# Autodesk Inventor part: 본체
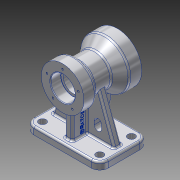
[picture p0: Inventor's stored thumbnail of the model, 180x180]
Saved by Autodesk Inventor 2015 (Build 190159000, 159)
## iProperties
Created: 2015-08
Part Number: 본체
Material: Aluminum 6061
Document SubType Name: Modeling
Designer: 601
Density: 2.7 g/cm^3
Appearance: Aluminum - Flat
Mass: 1058.96 g
Surface Area: 767.525 cm^2
Volume: 392.208 cm^3
Author: 601
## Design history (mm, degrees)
sketch "Sketch3"
  geometry: L1 (20, -5.906)-(20, -22.906); L2 (20, -22.906)-(16, -22.906); L3 (16, -22.906)-(16, -72.906); L4 (0, 0)-(0, -90); L5 (26, -95.906)-(26, -75.906); L6 (35, -5.906)-(35, -25.906); L7 (26, -95.906)-(40, -95.906); L8 (40, -95.906)-(40, -75.906); L9 (26.173, -31.002)-(35, -25.906); L10 (26.173, -59.428)-(40, -75.906); L11 (20, -17.072)-(20, -22.906); L12 (26.173, -31.002)-(26.173, -59.428); L13 (35, -5.906)-(20, -5.906); L14 (26, -75.906)-(19, -75.906); L15 (19, -75.906)-(19, -72.906); L16 (19, -72.906)-(16, -72.906)
  constraints: 32 end point, 7 vertical, 4 horizontal, 3 perpendicular
  dimensions: "d31" = 17 distance of L1.start L1.end; "d32" = 20 distance from line of L4.start L1; "d36" = 90 distance of L4.start L4.end; "d38" = 26 distance between parallel lines of L4 L5; "d39" = 20 distance of L6.start L6.end; "d40" = 35 distance between parallel lines of L4 L6; "d45" = 20 distance of L7.end L8.end; "d46" = 40 distance from line of L4 L7.end; "d132" = 90 distance between parallel lines of L7 L13; "d133" = 60 deg angle of L12 L9; "d134" = 40 deg angle of L12 L10; "d135" = 7 distance of L5.end L14.end; "d138" = 16 distance between parallel lines of L4 L3; "d139" = 50 distance between parallel lines of L2 L16; "d140" = 26.17342 distance between parallel lines of L4 L12
revolve "Revolution2" sketch "Sketch3" stored, may be unused: angle "d50" = 90 deg
workplane "Work Plane2"
sketch "Sketch7"
  geometry: L1 (-47, -85.906)-(47, -85.906); L2 (61, -71.906)-(61, -19.906); L3 (47, -5.906)-(-47, -5.906); L4 (-61, -19.906)-(-61, -71.906); C1 r 6 at (47, -71.906); C2 r 6 at (47, -19.906); C3 r 6 at (-47, -71.906); C4 r 6 at (-47, -19.906); A1 r 14 centre (-47, -19.906) between (-47, -5.906) and (-61, -19.906); A2 r 14 centre (47, -19.906) between (61, -19.906) and (47, -5.906); A3 r 14 centre (47, -71.906) between (47, -85.906) and (61, -71.906); A4 r 14 centre (-47, -71.906) between (-61, -71.906) and (-47, -85.906); 6 further points; 1 other entity
  constraints: 8 centre point, 8 end point, 8 point on circle, 8 tangent, 6 point on line, 5 equal radius, 2 horizontal alignment, 2 parallel, 1 coincident, 1 horizontal, 1 perpendicular, 1 vertical, 3 other
  dimensions: "d76" = 122 distance of point (-61, -5.906) point (61, -5.906); "d77" = 80 distance of point (61, -5.906) point (61, -85.906); "d78" = 80 dimension on L1; "d79" = 61 distance from line of point (0, 0) L4; "d80" = 14 radius of A1; "d81" = 12 diameter of C1; "d84" = 52 distance of C1.centre C2.centre; "d87" = 94 distance of C1.centre C3.centre
extrude "Extrusion2" join sketch "Sketch7" distance "d90" = 12; taper "d91" = 0 deg
workplane "Work Plane4"
sketch "Sketch8"
  geometry: L1 (108, 0)-(108, 12) reference; L2 (-14, 0)-(-14, 12) reference; L3 (0, 12)-(94, 12) reference; L4 (72.193, 82.904)-(98, 12); L5 (21.807, 82.904)-(-4, 12); L6 (-4, 12)-(98, 12); L7 (65, 30)-(65, 36); L8 (77, 30)-(77, 36); L9 (47, 90)-(47, 12); L10 (17.016, 36.433)-(17.016, 30.433); L11 (28.984, 36.433)-(28.984, 29.567); A1 r 26.173 centre (47, 90) between (72.193, 82.904) and (21.807, 82.904) reference; A2 r 26.173 centre (47, 90) between (21.807, 82.904) and (72.193, 82.904); A3 r 6 centre (71, 36) between (77, 36) and (65, 36); A4 r 6 centre (71, 30) between (65, 30) and (77, 30); A5 r 6 centre (23, 36) between (28.984, 35.567) and (17.016, 35.567); A6 r 6 centre (23, 30) between (17.016, 30.433) and (28.984, 30.433); 1 further point
  constraints: 18 point on circle, 16 end point, 6 point on line, 5 centre point, 3 tangent, 3 vertical, 1 concentric, 1 horizontal, 1 midpoint
  dimensions: "d93" = 10 distance from line of L1 L4.end; "d94" = 70 deg angle of L3 L4; "d95" = 10 horizontal distance of L2.start L5.end; "d96" = 70 deg angle of L3 L5; "d97" = 12 diameter of A3; "d100" = 12 diameter of A4; "d101" = 6 distance of A4.centre A3.centre; "d102" = 18 distance from line of L3 A4.centre; "d103" = 94 distance of L3.start L3.end (derived); "d104" = 23 horizontal distance of L3.end A4.centre; "d105" = 24 distance from line of L3 A3.centre; "d120" = 12 diameter of A5; "d123" = 48 distance of A3.centre A5.centre; "d124" = 24 distance from line of L3 A5.centre; "d191" = 48 distance of A4.centre A6.centre
extrude "Extrusion3" join sketch "Sketch8" stored distance "d106" = 12; taper "d107" = 0 deg
sketch "Sketch12"
  geometry: 6 further points
  constraints: 6 other
  dimensions: "d131" = 27 distance of point (0, 0) point (0, 27); "d141" = 0 horizontal distance of point (0, 0) point (0, 27); "d144" = 360 deg dimension on point (0, 0) point (0, 27) (derived)
hole "Hole1" sketch "Sketch12" at (0, 27), (-25.679, 8.343), (-15.87, -21.843), (15.87, -21.843), (25.679, 8.343) diameter "d146" = 3.242; stored, may be unused: countersink angle "d150" = 90 deg, drill point angle "d152" = 118 deg; dims "d147" = 10, "d148" = 4, "d149" = 2, "d151" = 13
fillet "Fillet1" dims "d166" = 5
sketch "Sketch13"
  geometry: 6 further points
  constraints: 6 other
  dimensions: "d153" = 33 distance of point (0, 33) point (0, 0); "d154" = 0 horizontal distance of point (0, 0) point (0, 33); "d157" = 360 deg dimension on point (0, 0) point (0, 33) (derived)
hole "Hole2" sketch "Sketch13" at (0, 33), (-31.385, 10.198), (-19.397, -26.698), (19.397, -26.698), (31.385, 10.198) diameter "d159" = 3.242; stored, may be unused: countersink angle "d163" = 90 deg, drill point angle "d165" = 118 deg; dims "d160" = 10, "d161" = 4, "d162" = 2, "d164" = 13
sketch "Sketch16"
  geometry: L1 (-90, -5.906)-(-78, -5.906) reference; L2 (-78, -19.906)-(-78, -5.906) reference; L3 (-78, -19.906)-(-78, -71.906) reference; L4 (-78, -85.906)-(-78, -71.906) reference; L5 (-90, -85.906)-(-78, -85.906) reference; L6 (-40, -77.726)-(-40, -95.906) reference; L7 (-27.343, -60.822)-(-38.83, -74.512) reference; L8 (-26.173, -33.889)-(-26.173, -57.608) reference; L9 (-32.5, -27.349)-(-28.673, -29.559) reference; L10 (-35, -5.906)-(-35, -23.019) reference; L11 (-35, -15.906)-(-78, -15.906); L12 (-40, -82.606)-(-78, -75.906); A1 r 5 centre (-35, -77.726) between (-38.83, -74.512) and (-40, -77.726) reference; A2 r 5 centre (-31.173, -57.608) between (-27.343, -60.822) and (-26.173, -57.608) reference; A3 r 5 centre (-31.173, -33.889) between (-26.173, -33.889) and (-28.673, -29.559) reference; A4 r 5 centre (-30, -23.019) between (-35, -23.019) and (-32.5, -27.349) reference; 1 further point
  constraints: 4 end point, 4 point on line, 1 horizontal
  dimensions: "d173" = 10 distance between parallel lines of L1 L11; "d174" = 10 distance of L4.start L12.end; "d175" = 80 deg angle of L4 L12
extrude "Extrusion6" join sketch "Sketch16" stored distance "d176" = 12; taper "d177" = 0 deg
fillet "Fillet3" dims "d179" = 3
sketch "Sketch17"
  geometry: L1 (15.906, -35)-(15.906, -75) reference; L2 (8.906, -78)-(19.906, -78) reference; L3 (28.762, -74.872)-(28.762, -33.393); L4 (28.762, -33.393)-(34.766, -33.393); L5 (34.766, -33.393)-(34.766, -74.872); L6 (34.766, -74.872)-(28.762, -74.872); 2 further points
  constraints: 2 other
  dimensions: "d180" = 16 distance from line of L1 point (31.906, -54); "d181" = 24 distance from line of L2 point (31.906, -54)
emboss "Emboss1" sketch "Sketch17" dims "d31" = 17, "d32" = 20, "d36" = 90, "d38" = 26, "d39" = 20, "d40" = 35, "d45" = 20, "d46" = 40, "d80" = 14, "d132" = 90, "d133" = 60 deg, "d134" = 40 deg, "d135" = 7, "d138" = 16, "d139" = 50, "d140" = 26.17342, "d182" = 0.5, "d183" = 0
chamfer "Chamfer1" distance "d184" = 1; stored, may be unused: second distance "d185" = 2, angle "d186" = 45 deg
chamfer "Chamfer2" distance "d187" = 1; stored, may be unused: second distance "d188" = 2, angle "d189" = 45 deg
fillet "Fillet4" dims "d190" = 0.3
body "Solid2"
other parameters: "d41" = 26, "d48" = 60 deg, "d49" = 40 deg
